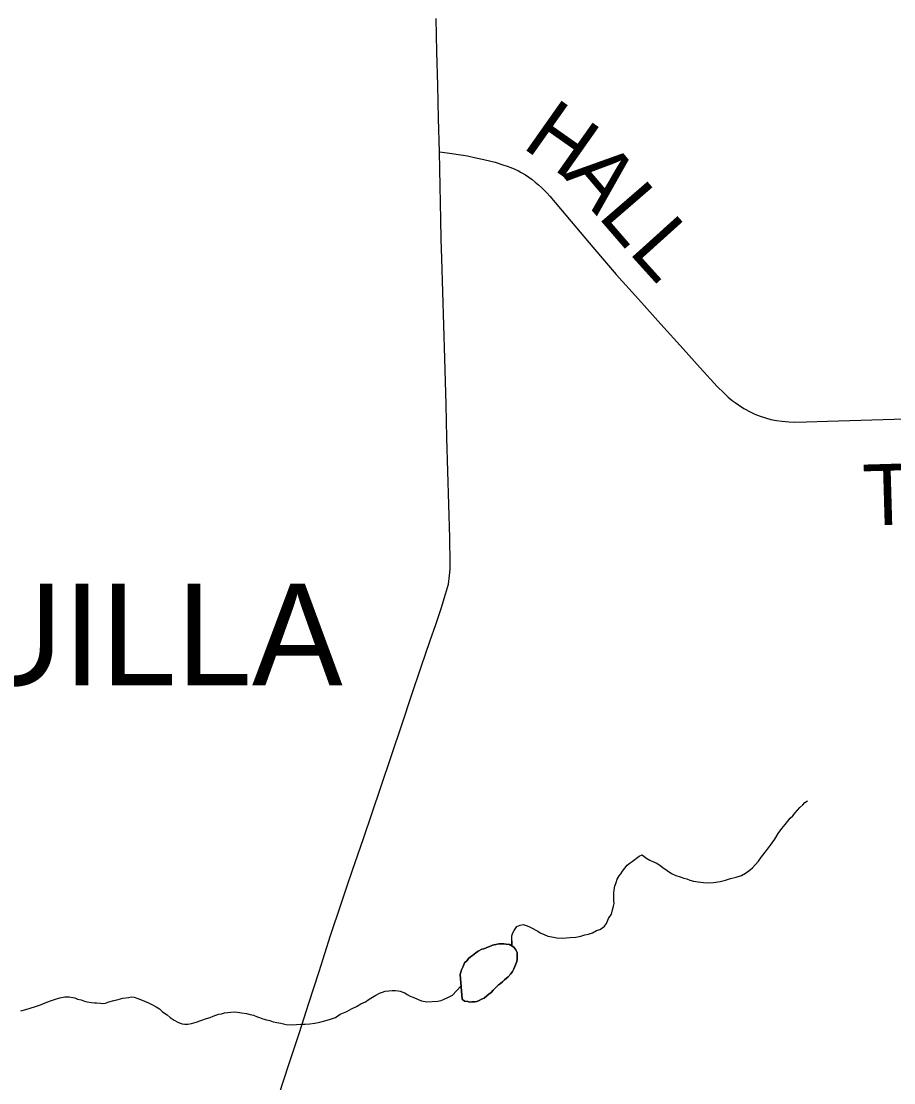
# Model space of a CAD drawing. Extents: x 103424 to 286016, y 38711 to 110967.
# Drawn here: x 156150 to 160467, y 86428 to 91682 of the extents above; entities that cross this region are included whole.
import ezdxf

# ---------------------------------------------------------------- set-up
doc = ezdxf.new("R2010")
doc.units = 0
for name, color, linetype in [('GM_X_Corporation_Text', 7, 'Continuous'), ('GM_X_Minor_Lake', 7, 'Continuous'), ('GM_X_Minor_River', 7, 'Continuous'), ('GM_X_Township_Road', 7, 'Continuous'), ('GM_X_Township_Road_Text', 7, 'Continuous')]:
    doc.layers.add(name, color=color, linetype=linetype)

msp = doc.modelspace()

# ---------------------------------------------------------------- linework, layer by layer
at = {"layer": 'GM_X_Minor_Lake'}
for points in [[(158603.6, 87050.4), (158603.4, 87062.5), (158603.2, 87072.6), (158596.9, 87086.6), (158586.6, 87098.6), (158566.2, 87112.3), (158550, 87114.1), (158537.9, 87115.9), (158525.8, 87115.6), (158513.7, 87115.4), (158497.6, 87113.1), (158481.5, 87108.8), (158471.5, 87104.6), (158461.5, 87100.3), (158439.5, 87091.9), (158429.4, 87089.7), (158411.4, 87079.2), (158399.5, 87071), (158383.5, 87058.5), (158373.6, 87052.3), (158363.6, 87044), (158355.7, 87033.8), (158343.9, 87021.5), (158336.1, 87003.2), (158328.3, 86986.9), (158322.6, 86970.6), (158321.3, 86963.3)], [(158321.3, 86963.3), (158322.6, 86970.6), (158328.3, 86986.9), (158336.1, 87003.2), (158343.9, 87021.5), (158355.7, 87033.8), (158363.6, 87044), (158373.6, 87052.3), (158383.5, 87058.5), (158399.5, 87071), (158411.4, 87079.2), (158429.4, 87089.7), (158439.5, 87091.9), (158461.5, 87100.3), (158471.5, 87104.6), (158481.5, 87108.8), (158497.6, 87113.1), (158513.7, 87115.4), (158525.8, 87115.6), (158537.9, 87115.9), (158550, 87114.1), (158566.2, 87112.3), (158586.6, 87098.6), (158596.9, 87086.6), (158603.2, 87072.6), (158603.4, 87062.5), (158603.6, 87050.4), (158603.8, 87040.3), (158602, 87028.1), (158596.3, 87011.9), (158586.5, 86991.5), (158580.7, 86979.2), (158572.8, 86967), (158559, 86952.6), (158541.1, 86938.1), (158531.2, 86927.9), (158521.2, 86919.6), (158511.3, 86913.4), (158495.4, 86896.9), (158485.5, 86886.6), (158475.6, 86874.3), (158463.7, 86866), (158453.7, 86857.8), (158439.8, 86847.4), (158427.8, 86841.2), (158415.8, 86834.9), (158403.8, 86830.6), (158393.7, 86828.4), (158379.6, 86828.2), (158369.5, 86828), (158359.4, 86829.8), (158343.2, 86831.6), (158330.9, 86841.4), (158321.3, 86963.3)], [(158321.3, 86963.3), (158330.9, 86841.4), (158343.2, 86831.6), (158359.4, 86829.8), (158369.5, 86828), (158379.6, 86828.2), (158393.7, 86828.4), (158403.8, 86830.6), (158415.8, 86834.9), (158427.8, 86841.2), (158439.8, 86847.4), (158453.7, 86857.8), (158463.7, 86866), (158475.6, 86874.3), (158485.5, 86886.6), (158495.4, 86896.9), (158511.3, 86913.4), (158521.2, 86919.6), (158531.2, 86927.9), (158541.1, 86938.1), (158559, 86952.6), (158572.8, 86967), (158580.7, 86979.2), (158586.5, 86991.5), (158596.3, 87011.9), (158602, 87028.1), (158603.8, 87040.3), (158603.6, 87050.4)]]:
    msp.add_lwpolyline(points, dxfattribs=at)
at = {"layer": 'GM_X_Minor_River'}
for points in [[(158577.3, 87130.2), (158577.3, 87104.8), (158577.5, 87143.3), (158577.3, 87155.4), (158583.1, 87169.7), (158588.9, 87181.9), (158602.7, 87202.4), (158618.7, 87208.7), (158632.8, 87211), (158653.1, 87205.3), (158665.3, 87199.5), (158681.6, 87191.7), (158695.9, 87183.8), (158706.1, 87178), (158718.3, 87170.1), (158736.6, 87162.3), (158754.9, 87154.6), (158775.1, 87150.9), (158799.5, 87145.3), (158825.7, 87143.7), (158866, 87146.5), (158894.2, 87149), (158918.4, 87153.5), (158938.4, 87159.9), (158956.5, 87164.3), (158976.6, 87170.7), (158996.6, 87181.1), (159012.6, 87187.5), (159026.6, 87195.8), (159036.5, 87204.1), (159046.4, 87216.4), (159056, 87240.8), (159069.8, 87263.3), (159075.5, 87283.6), (159081.2, 87301.9), (159082.9, 87316), (159082.7, 87330.2), (159082.4, 87348.3), (159082, 87366.5), (159083.8, 87382.7), (159087.5, 87401), (159093.2, 87419.2), (159099, 87435.5), (159108.8, 87451.8), (159116.6, 87462.1), (159124.5, 87476.4), (159136.3, 87490.7), (159148.2, 87505.1), (159162.1, 87517.4), (159172, 87523.7), (159207.9, 87550.6), (159221.9, 87556.9), (159240.3, 87541.1), (159260.7, 87529.3), (159281.1, 87519.6), (159295.3, 87515.8), (159311.6, 87504), (159323.9, 87494.1), (159346.4, 87478.3), (159366.8, 87464.5), (159389.2, 87454.8), (159409.5, 87447.1), (159427.8, 87441.4), (159444, 87437.6), (159458.2, 87431.8), (159476.5, 87426.1), (159498.7, 87422.5), (159525, 87418.9), (159549.3, 87417.3), (159575.5, 87419.8), (159607.7, 87424.4), (159633.8, 87431), (159659.9, 87439.5), (159688, 87446.1), (159714.1, 87454.6), (159734.1, 87465.1), (159750, 87477.5), (159767.9, 87491.9), (159781.8, 87506.3), (159797.6, 87524.8), (159813.3, 87547.3), (159837, 87578), (159856.7, 87604.6), (159878.4, 87633.3), (159896, 87661.9), (159913.7, 87686.5), (159929.5, 87707), (159943.3, 87723.4), (159955.2, 87737.7), (159967.1, 87750.1), (159978.9, 87764.4), (159990.8, 87776.7), (160002.7, 87791.1), (160016.6, 87803.5), (160026.4, 87815.8), (160040.4, 87824.1)], [(156541.2, 86822), (156553.4, 86820.2), (156567.4, 86822.5), (156583.5, 86828.8), (156607.6, 86835.3), (156629.7, 86839.7), (156651.8, 86846.2), (156679.9, 86850.7), (156696, 86853), (156708.2, 86851.3), (156726.4, 86845.5), (156740.7, 86839.7), (156759, 86832), (156779.3, 86824.2), (156799.6, 86814.5), (156818, 86804.7), (156834.3, 86794.9), (156848.7, 86779), (156871.1, 86765.3), (156887.5, 86751.4), (156905.9, 86737.6), (156924.3, 86727.8), (156936.4, 86724), (156946.6, 86720.2), (156958.8, 86718.4), (156974.9, 86718.6), (156993, 86721), (157015.1, 86727.5), (157039.1, 86736), (157067.2, 86746.6), (157085.3, 86750.9), (157099.3, 86757.2), (157113.3, 86763.6), (157127.4, 86767.9), (157141.4, 86770.1), (157155.5, 86774.4), (157203.8, 86779.3), (157220, 86777.6), (157240.3, 86773.9), (157264.5, 86770.3), (157282.8, 86766.6), (157299, 86762.9), (157313.2, 86757), (157329.4, 86751.3), (157345.7, 86745.5), (157364, 86739.8), (157380.2, 86736), (157396.4, 86730.2), (157414.6, 86726.5), (157434.9, 86722.9), (157461.2, 86717.3), (157485.5, 86715.7), (157511.7, 86716.2), (157533.8, 86718.6), (157554, 86718.9), (157578.2, 86719.4), (157602.3, 86723.8), (157626.5, 86728.3), (157652.6, 86734.8), (157680.7, 86743.4), (157704.7, 86751.9), (157728.7, 86768.5), (157760.7, 86781.2), (157784.7, 86793.8), (157808.7, 86806.3), (157830.7, 86818.8), (157852.7, 86829.3), (157870.6, 86841.8), (157888.6, 86852.2), (157904.6, 86862.6), (157922.6, 86871), (157936.6, 86877.3), (157950.6, 86881.6), (157968.8, 86883.9), (157984.9, 86884.2), (158001, 86884.5), (158015.2, 86882.7), (158025.3, 86880.9), (158037.5, 86877.1), (158047.6, 86873.2), (158059.9, 86865.4), (158074.1, 86857.5), (158092.4, 86849.8), (158110.8, 86842), (158131.1, 86834.3), (158157.4, 86828.7), (158211.8, 86831.7), (158227.9, 86836.1), (158241.9, 86842.4), (158259.9, 86850.8), (158273.9, 86857.1), (158283.9, 86861.3), (158325.8, 86905.7)], [(156148.4, 86784.6), (156172.5, 86791.1), (156194.6, 86797.6), (156220.7, 86806.2), (156244.7, 86814.7), (156268.8, 86823.2), (156294.8, 86833.7), (156318.9, 86842.2), (156341, 86848.7), (156365.1, 86853.2), (156387.3, 86853.6), (156405.5, 86849.9), (156415.6, 86848), (156427.9, 86842.2), (156446.1, 86838.5), (156462.3, 86832.7), (156476.5, 86828.9), (156496.8, 86825.2), (156512.9, 86823.5), (156523, 86823.7), (156541.2, 86822)]]:
    msp.add_lwpolyline(points, dxfattribs=at)
at = {"layer": 'GM_X_Township_Road'}
for points in [[(157424.8, 86366.4), (157475.9, 86523.4), (157524.5, 86672.8), (157573.1, 86822.1), (157623.6, 86979.2), (157652.2, 87068.2), (157680.8, 87157.1), (157733.3, 87313.7), (157761.4, 87397.5), (157789.5, 87481.3), (157842.8, 87637.5), (157886.1, 87764.4), (157929.4, 87891.3), (157981.8, 88047.9), (158034.1, 88204.4), (158081.3, 88345.4), (158128.5, 88486.5), (158173.2, 88616.9), (158200.8, 88696), (158228.4, 88775.1), (158249.1, 88846.2), (158263.5, 88895.8), (158268.9, 88938.2), (158271.8, 88970.8), (158271.5, 88999.4), (158270.8, 89125), (158266.1, 89290), (158261.3, 89455), (158256.5, 89620), (158251.7, 89785), (158248.4, 89899.1), (158245, 90013.3), (158240.3, 90178.3), (158235.6, 90343.3), (158230.9, 90508.3), (158228.1, 90604.3), (158225.4, 90700.4), (158222.6, 90865.5), (158221.2, 90950.7), (158219.7, 91036), (158215.3, 91201), (158211, 91366), (158206.6, 91531), (158202.2, 91696)], [(158219.7, 91036), (158257.6, 91030.9), (158280.8, 91027.7), (158357.2, 91015.4), (158399.6, 91007.1), (158439.4, 90998.8), (158472.7, 90990.4), (158494.7, 90984.6), (158532.6, 90972.4), (158553.8, 90965.4), (158572.4, 90958.3), (158591.9, 90950.7), (158609.8, 90941.7), (158623.1, 90934.2), (158644.5, 90921.5), (158661.1, 90910.4), (158677.5, 90898.7), (158693.3, 90886.4), (158708.7, 90873.5), (158723.5, 90860), (158737.9, 90845.9), (158751.7, 90831.4), (158764.8, 90816.3), (158871.6, 90690.4), (158978.4, 90564.6), (159036, 90496.7), (159093.6, 90428.9), (159204.1, 90306.3), (159314.7, 90183.7), (159425.2, 90061.1), (159509.6, 89967.5), (159594, 89874), (159628.4, 89842.1), (159648.5, 89821.8), (159667.5, 89806), (159683, 89794.8), (159698.3, 89783.9), (159726, 89765.7), (159760, 89746.7), (159780.1, 89738), (159805.8, 89727.8), (159832.7, 89718.9), (159859.6, 89711.2), (159887, 89706.2), (159914.9, 89702.4), (159947.2, 89699.6), (159975.7, 89697.7), (160035.7, 89699.5)], [(160035.7, 89699.5), (160139.4, 89702.4), (160304.3, 89707.7), (160469.3, 89712.9), (160634.3, 89718.2), (160735.4, 89721.4), (160836.5, 89724.6), (160952.7, 89727.6), (161068.9, 89730.7), (161208.8, 89734.3), (161348.7, 89738), (161464.1, 89741), (161575.6, 89742.8)]]:
    msp.add_lwpolyline(points, dxfattribs=at)

# ---------------------------------------------------------------- texts
at = {"layer": 'GM_X_Corporation_Text'}
msp.add_text('AQUILLA', height=503.12, rotation=0, dxfattribs=at).set_placement((154898.4, 88395.5))
at = {"layer": 'GM_X_Township_Road_Text'}
for s, height, rotation, p in [('H', 301.9, 324.8337, (158622.2, 91060.9)), ('A', 301.9, 310.2809, (158824.4, 90921.5)), ('L', 301.9, 310.8715, (158998.4, 90716.3)), ('L', 301.9, 312.0684, (159150.7, 90540.3)), ('T-109', 301.87, 1.652, (160317.9, 89185.8))]:
    msp.add_text(s, height=height, rotation=rotation, dxfattribs=at).set_placement(p)

doc.saveas('drawing.dxf')
